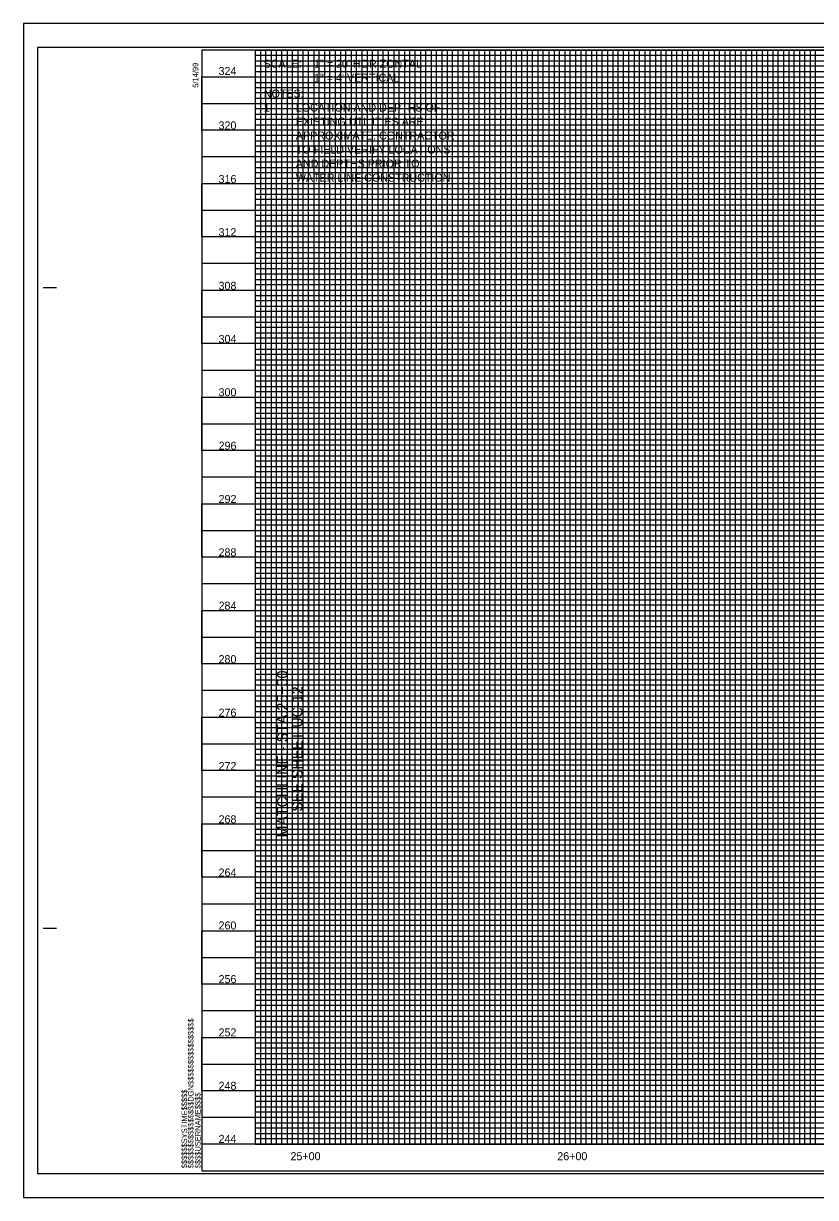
# Model space of a CAD drawing. Extents: x 3814791 to 3815465, y 1224203 to 1224643.
# Drawn here: x 3814791.3 to 3815088.1, y 1224203.2 to 1224643.2 of the extents above; entities that cross this region are included whole.
import ezdxf

# ---------------------------------------------------------------- set-up
doc = ezdxf.new("R2010")
doc.units = 0
for name, color, linetype in [('COGO Default Spiral', 7, 'Continuous'), ('Exist Roads EOP', 7, 'Continuous'), ('General Text and Text Box and Leader Line', 7, 'Continuous'), ('Pattern 49', 7, 'Continuous'), ('Profile Utility Text', 7, 'Continuous'), ('Scratch_Level_1', 7, 'Continuous'), ('Water Line Text and Text Box and Leader Line (St)', 7, 'Continuous'), ('Water Pump Station (St) CELL', 7, 'Continuous')]:
    doc.layers.add(name, color=color, linetype=linetype)

msp = doc.modelspace()

# ---------------------------------------------------------------- linework, layer by layer
at = {"layer": 'COGO Default Spiral'}
msp.add_line((3814898.11, 1224443.21), (3814898.11, 1224263.21), dxfattribs=at)
at = {"layer": 'Exist Roads EOP'}
for p, q in [((3814878.11, 1224633.21), (3815378.11, 1224633.21)), ((3815438.11, 1224561.21), (3814878.11, 1224561.21)), ((3814878.11, 1224561.21), (3814878.11, 1224559.21)), ((3814878.11, 1224559.21), (3815438.11, 1224559.21)), ((3815438.11, 1224551.21), (3814878.11, 1224551.21)), ((3814798.71, 1224544.21), (3814803.71, 1224544.21)), ((3814798.71, 1224304.21), (3814803.71, 1224304.21)), ((3815458.11, 1224223.21), (3814858.11, 1224223.21)), ((3814878.11, 1224223.21), (3815438.11, 1224223.21)), ((3814858.11, 1224213.21), (3814858.11, 1224213.21)), ((3814858.11, 1224213.21), (3814858.11, 1224213.21)), ((3814858.11, 1224213.21), (3814858.11, 1224213.21)), ((3814858.11, 1224213.21), (3814858.11, 1224213.21)), ((3814858.11, 1224213.21), (3814858.11, 1224213.21)), ((3814858.11, 1224213.21), (3814858.11, 1224213.21))]:
    msp.add_line(p, q, dxfattribs=at)
for points in [[(3815458.11, 1224633.21), (3814858.11, 1224633.21), (3814858.11, 1224213.21), (3815458.11, 1224213.21)], [(3814878.11, 1224633.21), (3814878.11, 1224223.21), (3815438.11, 1224223.21), (3815438.11, 1224578.19), (3815378.11, 1224578.19), (3815378.11, 1224633.21)]]:
    msp.add_lwpolyline(points, close=True, dxfattribs=at)
for points in [[(3814878.11, 1224633.21), (3814878.11, 1224223.21), (3814898.11, 1224223.21), (3814898.11, 1224633.21), (3814918.11, 1224633.21), (3814918.11, 1224223.21), (3814938.11, 1224223.21), (3814938.11, 1224633.21), (3814958.11, 1224633.21), (3814958.11, 1224223.21), (3814978.11, 1224223.21), (3814978.11, 1224633.21), (3814998.11, 1224633.21), (3814998.11, 1224223.21), (3815018.11, 1224223.21), (3815018.11, 1224633.21), (3815038.11, 1224633.21), (3815038.11, 1224223.21), (3815058.11, 1224223.21), (3815058.11, 1224633.21), (3815078.11, 1224633.21), (3815078.11, 1224223.21), (3815098.11, 1224223.21)], [(3814878.11, 1224633.21), (3814880.11, 1224633.21), (3814880.11, 1224223.21), (3814882.11, 1224223.21), (3814882.11, 1224633.21), (3814884.11, 1224633.21), (3814884.11, 1224223.21), (3814886.11, 1224223.21), (3814886.11, 1224633.21), (3814890.11, 1224633.21), (3814890.11, 1224223.21), (3814892.11, 1224223.21), (3814892.11, 1224633.21), (3814894.11, 1224633.21), (3814894.11, 1224223.21), (3814896.11, 1224223.21), (3814896.11, 1224633.21), (3814900.11, 1224633.21), (3814900.11, 1224223.21), (3814902.11, 1224223.21), (3814902.11, 1224633.21), (3814904.11, 1224633.21), (3814904.11, 1224223.21), (3814906.11, 1224223.21), (3814906.11, 1224633.21), (3814910.11, 1224633.21), (3814910.11, 1224223.21), (3814912.11, 1224223.21), (3814912.11, 1224633.21), (3814914.11, 1224633.21), (3814914.11, 1224223.21), (3814916.11, 1224223.21), (3814916.11, 1224633.21), (3814920.11, 1224633.21), (3814920.11, 1224223.21), (3814922.11, 1224223.21), (3814922.11, 1224633.21), (3814924.11, 1224633.21), (3814924.11, 1224223.21), (3814926.11, 1224223.21), (3814926.11, 1224633.21), (3814930.11, 1224633.21), (3814930.11, 1224223.21), (3814932.11, 1224223.21), (3814932.11, 1224633.21), (3814934.11, 1224633.21), (3814934.11, 1224223.21), (3814936.11, 1224223.21), (3814936.11, 1224633.21), (3814940.11, 1224633.21), (3814940.11, 1224223.21), (3814942.11, 1224223.21), (3814942.11, 1224633.21), (3814944.11, 1224633.21), (3814944.11, 1224223.21)], [(3815378.09, 1224631.21), (3814878.11, 1224631.21), (3814878.11, 1224629.21), (3815378.09, 1224629.21)], [(3814888.11, 1224223.21), (3814888.11, 1224633.21), (3814908.11, 1224633.21), (3814908.11, 1224223.21), (3814928.11, 1224223.21), (3814928.11, 1224633.21), (3814948.11, 1224633.21), (3814948.11, 1224223.21), (3814968.11, 1224223.21), (3814968.11, 1224633.21), (3814988.11, 1224633.21), (3814988.11, 1224223.21), (3815008.11, 1224223.21), (3815008.11, 1224633.21), (3815028.11, 1224633.21), (3815028.11, 1224223.21), (3815048.11, 1224223.21), (3815048.11, 1224633.21), (3815068.11, 1224633.21), (3815068.11, 1224223.21), (3815088.11, 1224223.21), (3815088.11, 1224633.21)], [(3814944.11, 1224223.21), (3814946.11, 1224223.21), (3814946.11, 1224633.21), (3814950.11, 1224633.21), (3814950.11, 1224223.21), (3814952.11, 1224223.21), (3814952.11, 1224633.21), (3814954.11, 1224633.21), (3814954.11, 1224223.21), (3814956.11, 1224223.21), (3814956.11, 1224633.21), (3814960.11, 1224633.21), (3814960.11, 1224223.21), (3814962.11, 1224223.21), (3814962.11, 1224633.21), (3814962.11, 1224633.21), (3814964.11, 1224633.21), (3814964.11, 1224223.21), (3814966.11, 1224223.21), (3814966.11, 1224633.21), (3814970.11, 1224633.21), (3814970.11, 1224223.21), (3814972.11, 1224223.21), (3814972.11, 1224633.21), (3814974.11, 1224633.21), (3814974.11, 1224223.21), (3814976.11, 1224223.21), (3814976.11, 1224633.21), (3814980.11, 1224633.21), (3814980.11, 1224223.21), (3814982.11, 1224223.21), (3814982.11, 1224633.21), (3814984.11, 1224633.21), (3814984.11, 1224223.21), (3814986.11, 1224223.21), (3814986.11, 1224633.21), (3814990.11, 1224633.21), (3814990.11, 1224223.21), (3814992.11, 1224223.21), (3814992.11, 1224633.21), (3814994.11, 1224633.21), (3814994.11, 1224223.21), (3814996.11, 1224223.21), (3814996.11, 1224633.21), (3815000.11, 1224633.21), (3815000.11, 1224223.21), (3815002.11, 1224223.21), (3815002.11, 1224633.21), (3815004.11, 1224633.21), (3815004.11, 1224223.21), (3815006.11, 1224223.21), (3815006.11, 1224633.21), (3815010.11, 1224633.21), (3815010.11, 1224223.21), (3815016.11, 1224223.21), (3815016.11, 1224633.21), (3815020.11, 1224633.21), (3815020.11, 1224223.21), (3815022.11, 1224223.21), (3815022.11, 1224633.21), (3815024.11, 1224633.21), (3815024.11, 1224223.21), (3815026.11, 1224223.21), (3815026.11, 1224633.21), (3815030.11, 1224633.21), (3815030.11, 1224223.21), (3815032.11, 1224223.21), (3815032.11, 1224633.21), (3815034.11, 1224633.21), (3815034.11, 1224223.21), (3815036.11, 1224223.21), (3815036.11, 1224633.21), (3815040.11, 1224633.21), (3815040.11, 1224223.21), (3815042.11, 1224223.21), (3815042.11, 1224633.21), (3815044.11, 1224633.21), (3815044.11, 1224223.21), (3815046.11, 1224223.21), (3815046.11, 1224633.21), (3815050.11, 1224633.21), (3815050.11, 1224223.21), (3815052.11, 1224223.21), (3815052.11, 1224633.21), (3815054.11, 1224633.21), (3815054.11, 1224223.21), (3815056.11, 1224223.21), (3815056.11, 1224633.21), (3815060.11, 1224633.21), (3815060.11, 1224223.21), (3815062.11, 1224223.21), (3815062.11, 1224633.21), (3815064.11, 1224633.21), (3815064.11, 1224223.21), (3815066.11, 1224223.21), (3815066.11, 1224633.21), (3815070.11, 1224633.21), (3815070.11, 1224223.21)], [(3815012.11, 1224633.21), (3815012.11, 1224223.21), (3815014.11, 1224223.21), (3815014.11, 1224633.21)], [(3815012.11, 1224632.97), (3815012.11, 1224223.21), (3815014.11, 1224223.21), (3815014.11, 1224632.97)], [(3815072.11, 1224633.21), (3815072.11, 1224223.21), (3815074.11, 1224223.21), (3815074.11, 1224633.21), (3815076.11, 1224633.21), (3815076.11, 1224223.21), (3815080.11, 1224223.21), (3815080.11, 1224633.21), (3815082.11, 1224633.21), (3815082.11, 1224223.21), (3815084.11, 1224223.21), (3815084.11, 1224633.21), (3815086.11, 1224633.21), (3815086.11, 1224223.21)], [(3815378.09, 1224627.21), (3814878.11, 1224627.21), (3814878.11, 1224625.21), (3815378.09, 1224625.21)], [(3815378.09, 1224603.21), (3814858.15, 1224603.21), (3814858.15, 1224623.19), (3815378.09, 1224623.19)], [(3815378.09, 1224620.91), (3814878.11, 1224620.91), (3814878.11, 1224619.21), (3815378.09, 1224619.21)], [(3815378.09, 1224617.21), (3814878.11, 1224617.21), (3814878.11, 1224615.21), (3815378.09, 1224615.21)], [(3814858.11, 1224613.21), (3815378.09, 1224613.21)], [(3815378.09, 1224611.21), (3814878.11, 1224611.21), (3814878.11, 1224609.21), (3815378.09, 1224609.21)], [(3815378.11, 1224607.21), (3814878.11, 1224607.21), (3814878.11, 1224605.21), (3815378.09, 1224605.21)], [(3815378.09, 1224601.21), (3814878.11, 1224601.21), (3814878.11, 1224599.21), (3815378.09, 1224599.21)], [(3815378.09, 1224597.21), (3814878.11, 1224597.21), (3814878.11, 1224595.21), (3815378.09, 1224595.21)], [(3815378.09, 1224593.21), (3814858.11, 1224593.21), (3814858.11, 1224573.19), (3815458.11, 1224573.19)], [(3815378.09, 1224591.21), (3814878.11, 1224591.21), (3814878.11, 1224589.21), (3815378.09, 1224589.21)], [(3815378.09, 1224587.21), (3814878.11, 1224587.21), (3814878.11, 1224585.21), (3815378.09, 1224585.21)], [(3815458.11, 1224563.21), (3814858.11, 1224563.21), (3814858.11, 1224583.21), (3815378.09, 1224583.21)], [(3815378.09, 1224581.21), (3814878.11, 1224581.21), (3814878.11, 1224579.21), (3815378.09, 1224579.21)], [(3815438.11, 1224577.21), (3814878.11, 1224577.21), (3814878.11, 1224577.21), (3814878.11, 1224569.21), (3815438.11, 1224569.21)], [(3815438.11, 1224577.21), (3814878.11, 1224577.21), (3814878.11, 1224577.21), (3814878.11, 1224569.21), (3815458.11, 1224569.21)], [(3814878.11, 1224575.21), (3815438.11, 1224575.21)], [(3815438.11, 1224571.21), (3814878.11, 1224571.21)], [(3815438.11, 1224567.21), (3814878.11, 1224567.21), (3814878.11, 1224565.21), (3815438.11, 1224565.21)], [(3815438.11, 1224557.21), (3814878.11, 1224557.21), (3814878.11, 1224555.21), (3815438.11, 1224555.21)], [(3815458.11, 1224553.21), (3814858.11, 1224553.21), (3814858.11, 1224533.21), (3815458.11, 1224533.21)], [(3815438.11, 1224549.21), (3814878.11, 1224549.21), (3814878.11, 1224547.21), (3815438.11, 1224547.21)], [(3815458.11, 1224523.21), (3814858.11, 1224523.21), (3814858.11, 1224543.21), (3815458.11, 1224543.21)], [(3815438.11, 1224545.21), (3814878.11, 1224545.21)], [(3814878.11, 1224541.21), (3815438.11, 1224541.21)], [(3815438.11, 1224539.21), (3814878.11, 1224539.21), (3814878.11, 1224537.21), (3815438.11, 1224537.21)], [(3815438.11, 1224535.21), (3814878.11, 1224535.21), (3814878.11, 1224531.21), (3815438.11, 1224531.21)], [(3815438.11, 1224529.21), (3814878.11, 1224529.21), (3814878.11, 1224527.21), (3815438.11, 1224527.21)], [(3815438.11, 1224525.21), (3814878.11, 1224525.21), (3814878.11, 1224521.21), (3815438.11, 1224521.21)], [(3815438.11, 1224519.21), (3814878.11, 1224519.21), (3814878.11, 1224517.21), (3815438.11, 1224517.21)], [(3815458.11, 1224513.21), (3814858.11, 1224513.21), (3814858.11, 1224493.21), (3815458.11, 1224493.21)], [(3815438.11, 1224515.21), (3814878.11, 1224515.21), (3814878.11, 1224511.21), (3815438.11, 1224511.21)], [(3815438.11, 1224509.21), (3814878.11, 1224509.21), (3814878.11, 1224507.21), (3815438.11, 1224507.21)], [(3815458.11, 1224483.21), (3814858.11, 1224483.21), (3814858.11, 1224503.21), (3815458.11, 1224503.21)], [(3815438.11, 1224505.21), (3814878.11, 1224505.21), (3814878.11, 1224501.21), (3815438.11, 1224501.21)], [(3815438.11, 1224499.21), (3814878.11, 1224499.21), (3814878.11, 1224497.21), (3815438.11, 1224497.21)], [(3815438.11, 1224495.21), (3814878.11, 1224495.21), (3814878.11, 1224491.21), (3815438.11, 1224491.21)], [(3815438.11, 1224489.21), (3814878.11, 1224489.21), (3814878.11, 1224487.21), (3815438.11, 1224487.21)], [(3815438.11, 1224485.21), (3814878.11, 1224485.21), (3814878.11, 1224481.21), (3815438.11, 1224481.21)], [(3815438.11, 1224479.21), (3814878.11, 1224479.21), (3814878.11, 1224477.21), (3815438.11, 1224477.21)], [(3815458.11, 1224473.21), (3814858.11, 1224473.21), (3814858.11, 1224453.21), (3815458.11, 1224453.21)], [(3815438.11, 1224475.21), (3814878.11, 1224475.21), (3814878.11, 1224471.21), (3815438.11, 1224471.21)], [(3815438.11, 1224469.21), (3814878.11, 1224469.21), (3814878.11, 1224467.21), (3815438.11, 1224467.21)], [(3815458.11, 1224443.21), (3814858.11, 1224443.21), (3814858.11, 1224463.21), (3815458.11, 1224463.21)], [(3815438.11, 1224465.21), (3814878.11, 1224465.21), (3814878.11, 1224461.21), (3815438.11, 1224461.21)], [(3815438.11, 1224459.21), (3814878.11, 1224459.21), (3814878.11, 1224457.21), (3815438.11, 1224457.21)], [(3815438.11, 1224455.21), (3814878.11, 1224455.21), (3814878.11, 1224451.21), (3815438.11, 1224451.21)], [(3815438.11, 1224449.21), (3814878.11, 1224449.21), (3814878.11, 1224447.21), (3815438.11, 1224447.21)], [(3815438.11, 1224445.21), (3814878.11, 1224445.21), (3814878.11, 1224441.21), (3815438.11, 1224441.21)], [(3815438.11, 1224439.21), (3814878.11, 1224439.21), (3814878.11, 1224437.21), (3815438.11, 1224437.21)], [(3815458.11, 1224433.21), (3814858.11, 1224433.21), (3814858.11, 1224413.21), (3815458.11, 1224413.21)], [(3815438.11, 1224435.21), (3814878.11, 1224435.21), (3814878.11, 1224431.21), (3815438.11, 1224431.21)], [(3815438.11, 1224429.21), (3814878.11, 1224429.21), (3814878.11, 1224427.21), (3815438.11, 1224427.21)], [(3815458.11, 1224403.21), (3814858.11, 1224403.21), (3814858.11, 1224423.21), (3815458.11, 1224423.21)], [(3815438.11, 1224425.21), (3814878.11, 1224425.21)], [(3814878.11, 1224421.21), (3815438.11, 1224421.21)], [(3815438.11, 1224419.21), (3814878.11, 1224419.21), (3814878.11, 1224417.21), (3815438.11, 1224417.21)], [(3815438.11, 1224415.21), (3814878.11, 1224415.21), (3814878.11, 1224411.21), (3815438.11, 1224411.21)], [(3815438.11, 1224409.21), (3814878.11, 1224409.21), (3814878.11, 1224407.21), (3815438.11, 1224407.21)], [(3815438.11, 1224405.21), (3814878.11, 1224405.21), (3814878.11, 1224401.21), (3815438.11, 1224401.21)], [(3815438.11, 1224399.21), (3814878.11, 1224399.21), (3814878.11, 1224397.21), (3815438.11, 1224397.21)], [(3815458.11, 1224393.21), (3814858.11, 1224393.21), (3814858.11, 1224373.21), (3815458.11, 1224373.21)], [(3815438.11, 1224395.21), (3814878.11, 1224395.21), (3814878.11, 1224391.21), (3815438.11, 1224391.21)], [(3815438.11, 1224389.21), (3814878.11, 1224389.21), (3814878.11, 1224387.21), (3815438.11, 1224387.21)], [(3815438.11, 1224385.21), (3814878.11, 1224385.21), (3814878.11, 1224381.21), (3815438.11, 1224381.21)], [(3815458.11, 1224363.21), (3814858.11, 1224363.21), (3814858.11, 1224383.21), (3815458.11, 1224383.21)], [(3815438.11, 1224379.21), (3814878.11, 1224379.21), (3814878.11, 1224377.21), (3815438.11, 1224377.21)], [(3815438.11, 1224375.21), (3814878.11, 1224375.21), (3814878.11, 1224371.21), (3815438.11, 1224371.21)], [(3815438.11, 1224369.21), (3814878.11, 1224369.21), (3814878.11, 1224367.21), (3815438.11, 1224367.21)], [(3815438.11, 1224365.21), (3814878.11, 1224365.21), (3814878.11, 1224361.21), (3815438.11, 1224361.21)], [(3815438.11, 1224359.21), (3814878.11, 1224359.21), (3814878.11, 1224357.21), (3815438.11, 1224357.21)], [(3815458.11, 1224353.21), (3814858.11, 1224353.21), (3814858.11, 1224333.21), (3815458.11, 1224333.21)], [(3815438.11, 1224355.21), (3814878.11, 1224355.21), (3814878.11, 1224351.21), (3815438.11, 1224351.21)], [(3815438.11, 1224349.21), (3814878.11, 1224349.21), (3814878.11, 1224347.21), (3815438.11, 1224347.21)], [(3815438.11, 1224345.21), (3814878.11, 1224345.21), (3814878.11, 1224341.21), (3815438.11, 1224341.21)], [(3815458.11, 1224323.21), (3814858.11, 1224323.21), (3814858.11, 1224343.21), (3815458.11, 1224343.21)], [(3815438.11, 1224339.21), (3814878.11, 1224339.21), (3814878.11, 1224337.21), (3815438.11, 1224337.21)], [(3815438.11, 1224335.21), (3814878.11, 1224335.21), (3814878.11, 1224331.21), (3815438.11, 1224331.21)], [(3815438.11, 1224329.21), (3814878.11, 1224329.21), (3814878.11, 1224327.21), (3815438.11, 1224327.21)], [(3815438.11, 1224325.21), (3814878.11, 1224325.21), (3814878.11, 1224321.21), (3815438.11, 1224321.21)], [(3815438.11, 1224319.21), (3814878.11, 1224319.21), (3814878.11, 1224317.21), (3815438.11, 1224317.21)], [(3815458.11, 1224313.21), (3814858.11, 1224313.21), (3814858.11, 1224293.21), (3815458.11, 1224293.21)], [(3815438.11, 1224315.21), (3814878.11, 1224315.21), (3814878.11, 1224311.21), (3815438.11, 1224311.21)], [(3815438.11, 1224309.21), (3814878.11, 1224309.21), (3814878.11, 1224307.21), (3815438.11, 1224307.21)], [(3815438.11, 1224305.21), (3814878.11, 1224305.21)], [(3815458.11, 1224283.21), (3814858.11, 1224283.21), (3814858.11, 1224303.21), (3815458.11, 1224303.21)], [(3814878.11, 1224301.21), (3815438.11, 1224301.21)], [(3815438.11, 1224299.21), (3814878.11, 1224299.21), (3814878.11, 1224297.21), (3815438.11, 1224297.21)], [(3815438.11, 1224295.21), (3814878.11, 1224295.21)], [(3814878.11, 1224291.21), (3815438.11, 1224291.21)], [(3815438.11, 1224289.21), (3814878.11, 1224289.21), (3814878.11, 1224287.21), (3815438.11, 1224287.21)], [(3815438.11, 1224285.21), (3814878.11, 1224285.21), (3814878.11, 1224281.21), (3815438.11, 1224281.21)], [(3815438.11, 1224279.21), (3814878.11, 1224279.21), (3814878.11, 1224277.21), (3815438.11, 1224277.21)], [(3815438.11, 1224275.21), (3814878.11, 1224275.21), (3814878.11, 1224271.21), (3815438.11, 1224271.21)], [(3815458.11, 1224273.21), (3814858.11, 1224273.21), (3814858.11, 1224253.21), (3815458.11, 1224253.21)], [(3815438.11, 1224269.21), (3814878.11, 1224269.21), (3814878.11, 1224267.21), (3815438.11, 1224267.21)], [(3815438.11, 1224265.21), (3814878.11, 1224265.21), (3814878.11, 1224261.21), (3815438.11, 1224261.21)], [(3815458.11, 1224243.21), (3814858.11, 1224243.21), (3814858.11, 1224263.21), (3815458.11, 1224263.21)], [(3815438.11, 1224259.21), (3814878.11, 1224259.21), (3814878.11, 1224257.21), (3815438.11, 1224257.21)], [(3815438.11, 1224255.21), (3814878.11, 1224255.21), (3814878.11, 1224251.21), (3815438.11, 1224251.21)], [(3815438.11, 1224249.21), (3814878.11, 1224249.21), (3814878.11, 1224247.21), (3815438.11, 1224247.21)], [(3815438.11, 1224245.21), (3814878.11, 1224245.21), (3814878.11, 1224241.21), (3815438.11, 1224241.21)], [(3815438.11, 1224239.21), (3814878.11, 1224239.21), (3814878.11, 1224237.21), (3815438.11, 1224237.21)], [(3815438.11, 1224235.21), (3814878.11, 1224235.21), (3814878.11, 1224231.21), (3815438.11, 1224231.21)], [(3815458.11, 1224233.21), (3814858.11, 1224233.21)], [(3815438.11, 1224229.21), (3814878.11, 1224229.21), (3814878.11, 1224227.21), (3815438.11, 1224227.21)], [(3815438.11, 1224225.21), (3814878.11, 1224225.21)], [(3814873.11, 1224213.21), (3814873.11, 1224213.21)]]:
    msp.add_lwpolyline(points, dxfattribs=at)
at = {"layer": 'Pattern 49'}
msp.add_lwpolyline([(3815463.11, 1224634.23), (3814796.51, 1224634.23), (3814796.51, 1224212.19), (3815463.11, 1224212.19)], close=True, dxfattribs=at)
at = {"layer": 'Scratch_Level_1'}
msp.add_lwpolyline([(3815464.91, 1224643.21), (3814791.31, 1224643.21), (3814791.31, 1224203.21), (3815464.91, 1224203.21)], close=True, dxfattribs=at)

# ---------------------------------------------------------------- texts
at = {"layer": 'Exist Roads EOP'}
for s, p in [('5/14/99', (3814856.81, 1224619.13)), ('$$$$$$$$$$$$$$$$DGN$$$$$$$$$$$$$$$$', (3814855.05, 1224214.15)), ('$$$$$$SYSTIME$$$$$', (3814852.63, 1224214.15)), ('$$$$USERNAME$$$$', (3814857.68, 1224214.16))]:
    msp.add_text(s, height=2.1, rotation=90, dxfattribs=at).set_placement(p)
at = {"layer": 'General Text and Text Box and Leader Line'}
for s, p in [('324', (3814864.41, 1224623.89)), ('320', (3814864.41, 1224603.51)), ('316', (3814864.41, 1224583.41)), ('312', (3814864.41, 1224563.47)), ('308', (3814864.41, 1224543.4)), ('304', (3814864.41, 1224523.47)), ('300', (3814864.41, 1224503.5)), ('296', (3814864.41, 1224483.47)), ('292', (3814864.41, 1224463.51)), ('288', (3814864.41, 1224443.51)), ('284', (3814864.41, 1224423.5)), ('280', (3814864.41, 1224403.47)), ('276', (3814864.41, 1224383.43)), ('272', (3814864.41, 1224363.41)), ('268', (3814864.41, 1224343.46)), ('264', (3814864.41, 1224323.5)), ('260', (3814864.41, 1224303.66)), ('256', (3814864.41, 1224283.55)), ('252', (3814864.41, 1224263.59)), ('248', (3814864.41, 1224243.59)), ('244', (3814864.41, 1224223.68))]:
    msp.add_text(s, height=3, dxfattribs=at).set_placement(p)
at = {"layer": 'Profile Utility Text'}
for s, p in [('SCALE: ', (3814881.28, 1224626.62)), ('1" = 20\' HORIZONTAL', (3814900.19, 1224626.62)), ('1" = 4\' VERTICAL', (3814900.19, 1224621.37)), ('NOTES:', (3814881.36, 1224615.43)), ('1.', (3814881.36, 1224610.18)), ('LOCATION AND DEPTHS OF', (3814893.36, 1224610.18)), ('EXISTING UTILITIES ARE', (3814893.36, 1224604.94)), ('APPROXIMATE. CONTRACTOR', (3814893.36, 1224599.69)), ('TO FIELD VERIFY LOCATIONS', (3814893.36, 1224594.44)), ('AND DEPTHS PRIOR TO', (3814893.36, 1224589.19)), ('WATER LINE CONSTRUCTION.', (3814893.36, 1224583.94))]:
    msp.add_text(s, height=3, dxfattribs=at).set_placement(p)
at = {"layer": 'Water Line Text and Text Box and Leader Line (St)'}
for s, p in [('MATCHLINE - STA.25+00', (3814890.27, 1224338.14)), ('SEE SHEET UC-12', (3814895.87, 1224347.81))]:
    msp.add_text(s, height=4, rotation=90, dxfattribs=at).set_placement(p)
at = {"layer": 'Water Pump Station (St) CELL'}
for s, p in [('25+00', (3814891.36, 1224217.19)), ('26+00', (3814991.34, 1224217.19))]:
    msp.add_text(s, height=3, dxfattribs=at).set_placement(p)

doc.saveas('drawing.dxf')
